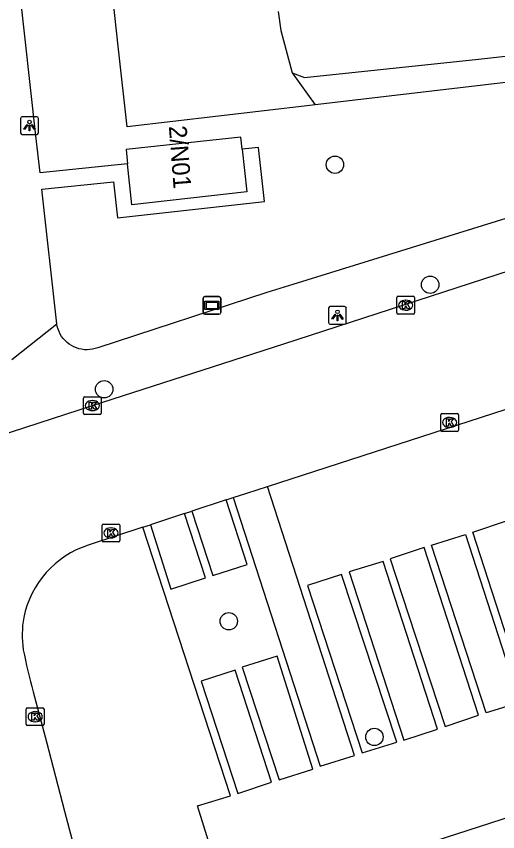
# Model space of a CAD drawing. Extents: x 161253 to 161848, y 384872 to 385383.
# Drawn here: x 161425.87 to 161452.98, y 385046.88 to 385092.79 of the extents above; entities that cross this region are included whole.
import ezdxf

# ---------------------------------------------------------------- set-up
doc = ezdxf.new("R2010")
doc.units = 0
for name, color, linetype in [('IMGEO_Boom', 7, 'Continuous'), ('IMGEO_Groenvoorziening', 7, 'Continuous'), ('IMGEO_Hek', 7, 'Continuous'), ('IMGEO_Kolk', 7, 'Continuous'), ('IMGEO_Lichtpunt', 7, 'Continuous'), ('IMGEO_Pand', 7, 'Continuous'), ('IMGEO_Pand_nummerreeks', 7, 'Continuous'), ('IMGEO_Parkeervlak_open', 7, 'Continuous'), ('IMGEO_Rijbaan_lokaal_open', 7, 'Continuous'), ('IMGEO_Verklikker', 7, 'Continuous'), ('IMGEO_Voetpad_open', 7, 'Continuous')]:
    doc.layers.add(name, color=color, linetype=linetype)

msp = doc.modelspace()

# ---------------------------------------------------------------- linework, layer by layer
at = {"layer": 'IMGEO_Boom'}
for centre in [(161443.813, 385084.433), (161449.173, 385077.674), (161430.819, 385071.789), (161437.837, 385058.731), (161446.031, 385052.213)]:
    msp.add_circle(centre, 0.489, dxfattribs=at)
at = {"layer": 'IMGEO_Groenvoorziening'}
for points in [[(161442.697, 385087.805), (161442.398, 385087.77), (161432.106, 385086.565), (161431.628, 385090.94), (161430.517, 385101.115), (161429.745, 385108.177), (161428.464, 385119.908), (161427.548, 385128.296), (161426.244, 385140.237), (161425.338, 385148.53), (161424.044, 385160.38), (161423.135, 385168.705), (161419.633, 385200.77)], [(161440.609, 385093.05), (161440.759, 385091.997), (161441.4, 385089.603)], [(161441.4, 385089.603), (161442.1, 385089.349), (161451.889, 385090.373), (161455.584, 385090.791), (161465.36, 385092.132), (161465.416, 385092.972)], [(161484.879, 385092.744), (161470.726, 385091.087), (161442.697, 385087.805)], [(161441.4, 385089.603), (161442.697, 385087.805)]]:
    msp.add_lwpolyline(points, dxfattribs=at)
at = {"layer": 'IMGEO_Hek'}
for points in [[(161431.628, 385090.94), (161430.517, 385101.115)], [(161432.106, 385086.565), (161431.628, 385090.94)], [(161470.726, 385091.087), (161442.697, 385087.805)], [(161442.398, 385087.77), (161432.106, 385086.565)], [(161442.697, 385087.805), (161442.398, 385087.77)]]:
    msp.add_lwpolyline(points, dxfattribs=at)
at = {"layer": 'IMGEO_Kolk'}
for p, q in [((161447.372, 385077.022), (161448.224, 385077.022)), ((161447.297, 385076.096), (161447.297, 385076.948)), ((161447.785, 385076.802), (161447.81, 385076.802)), ((161448.298, 385076.948), (161448.298, 385076.096)), ((161447.808, 385076.242), (161447.783, 385076.242)), ((161448.224, 385076.022), (161447.372, 385076.022)), ((161429.656, 385070.444), (161429.656, 385071.296)), ((161429.731, 385071.37), (161430.583, 385071.37)), ((161430.144, 385071.15), (161430.169, 385071.15)), ((161430.657, 385071.296), (161430.657, 385070.444)), ((161430.167, 385070.59), (161430.142, 385070.59)), ((161430.583, 385070.37), (161429.731, 385070.37)), ((161449.769, 385069.494), (161449.769, 385070.346)), ((161449.844, 385070.42), (161450.696, 385070.42)), ((161450.257, 385070.2), (161450.282, 385070.2)), ((161450.77, 385070.346), (161450.77, 385069.494)), ((161450.696, 385069.42), (161449.844, 385069.42)), ((161450.28, 385069.64), (161450.255, 385069.64)), ((161430.776, 385064.203), (161431.628, 385064.203)), ((161430.701, 385063.277), (161430.701, 385064.129)), ((161431.189, 385063.983), (161431.214, 385063.983)), ((161431.702, 385064.129), (161431.702, 385063.277)), ((161431.212, 385063.423), (161431.187, 385063.423)), ((161431.628, 385063.203), (161430.776, 385063.203)), ((161426.433, 385052.926), (161426.433, 385053.778)), ((161426.508, 385053.852), (161427.36, 385053.852)), ((161426.921, 385053.632), (161426.946, 385053.632)), ((161427.434, 385053.778), (161427.434, 385052.926)), ((161427.36, 385052.852), (161426.508, 385052.852)), ((161426.944, 385053.072), (161426.919, 385053.072))]:
    msp.add_line(p, q, dxfattribs=at)
for points in [[(161447.372, 385077.022), (161448.224, 385077.022)], [(161447.297, 385076.096), (161447.297, 385076.948)], [(161447.618, 385076.722), (161447.741, 385076.722), (161447.741, 385076.571), (161447.871, 385076.722), (161448.035, 385076.722), (161447.889, 385076.571), (161448.042, 385076.322), (161447.89, 385076.322), (161447.805, 385076.486), (161447.741, 385076.419), (161447.741, 385076.322), (161447.618, 385076.322), (161447.618, 385076.722)], [(161448.298, 385076.948), (161448.298, 385076.096)], [(161448.224, 385076.022), (161447.372, 385076.022)], [(161429.656, 385070.444), (161429.656, 385071.296)], [(161429.731, 385071.37), (161430.583, 385071.37)], [(161429.977, 385071.07), (161430.1, 385071.07), (161430.1, 385070.919), (161430.23, 385071.07), (161430.394, 385071.07), (161430.248, 385070.919), (161430.401, 385070.67), (161430.249, 385070.67), (161430.164, 385070.834), (161430.1, 385070.767), (161430.1, 385070.67), (161429.977, 385070.67), (161429.977, 385071.07)], [(161430.657, 385071.296), (161430.657, 385070.444)], [(161430.583, 385070.37), (161429.731, 385070.37)], [(161449.769, 385069.494), (161449.769, 385070.346)], [(161449.844, 385070.42), (161450.696, 385070.42)], [(161450.09, 385070.12), (161450.213, 385070.12), (161450.213, 385069.969), (161450.343, 385070.12), (161450.507, 385070.12), (161450.361, 385069.969), (161450.514, 385069.72), (161450.362, 385069.72), (161450.277, 385069.884), (161450.213, 385069.817), (161450.213, 385069.72), (161450.09, 385069.72), (161450.09, 385070.12)], [(161450.77, 385070.346), (161450.77, 385069.494)], [(161450.696, 385069.42), (161449.844, 385069.42)], [(161430.776, 385064.203), (161431.628, 385064.203)], [(161430.701, 385063.277), (161430.701, 385064.129)], [(161431.022, 385063.903), (161431.145, 385063.903), (161431.145, 385063.752), (161431.275, 385063.903), (161431.439, 385063.903), (161431.293, 385063.752), (161431.446, 385063.503), (161431.294, 385063.503), (161431.209, 385063.667), (161431.145, 385063.6), (161431.145, 385063.503), (161431.022, 385063.503), (161431.022, 385063.903)], [(161431.702, 385064.129), (161431.702, 385063.277)], [(161431.628, 385063.203), (161430.776, 385063.203)], [(161426.433, 385052.926), (161426.433, 385053.778)], [(161426.508, 385053.852), (161427.36, 385053.852)], [(161427.434, 385053.778), (161427.434, 385052.926)], [(161426.754, 385053.552), (161426.877, 385053.552), (161426.877, 385053.401), (161427.007, 385053.552), (161427.171, 385053.552), (161427.025, 385053.401), (161427.178, 385053.152), (161427.026, 385053.152), (161426.941, 385053.316), (161426.877, 385053.249), (161426.877, 385053.152), (161426.754, 385053.152), (161426.754, 385053.552)], [(161427.36, 385052.852), (161426.508, 385052.852)]]:
    msp.add_lwpolyline(points, dxfattribs=at)
for centre, start, end in [((161447.374, 385076.946), 91.552, 178.448), ((161447.374, 385076.946), 91.552, 178.448), ((161448.222, 385076.946), 1.552, 88.448), ((161448.222, 385076.946), 1.552, 88.448), ((161447.374, 385076.098), 181.552, 268.448), ((161447.374, 385076.098), 181.552, 268.448), ((161448.222, 385076.098), 271.552, 358.448), ((161448.222, 385076.098), 271.552, 358.448), ((161429.733, 385071.294), 91.552, 178.448), ((161429.733, 385071.294), 91.552, 178.448), ((161430.581, 385071.294), 1.552, 88.448), ((161430.581, 385071.294), 1.552, 88.448), ((161429.733, 385070.446), 181.552, 268.448), ((161429.733, 385070.446), 181.552, 268.448), ((161430.581, 385070.446), 271.552, 358.448), ((161430.581, 385070.446), 271.552, 358.448), ((161449.846, 385070.344), 91.552, 178.448), ((161449.846, 385070.344), 91.552, 178.448), ((161450.694, 385070.344), 1.552, 88.448), ((161450.694, 385070.344), 1.552, 88.448), ((161449.846, 385069.496), 181.552, 268.448), ((161449.846, 385069.496), 181.552, 268.448), ((161450.694, 385069.496), 271.552, 358.448), ((161450.694, 385069.496), 271.552, 358.448), ((161430.778, 385064.127), 91.552, 178.448), ((161430.778, 385064.127), 91.552, 178.448), ((161431.626, 385064.127), 1.552, 88.448), ((161431.626, 385064.127), 1.552, 88.448), ((161430.778, 385063.279), 181.552, 268.448), ((161430.778, 385063.279), 181.552, 268.448), ((161431.626, 385063.279), 271.552, 358.448), ((161431.626, 385063.279), 271.552, 358.448), ((161426.51, 385053.776), 91.552, 178.448), ((161426.51, 385053.776), 91.552, 178.448), ((161427.358, 385053.776), 1.552, 88.448), ((161427.358, 385053.776), 1.552, 88.448), ((161426.51, 385052.928), 181.552, 268.448), ((161426.51, 385052.928), 181.552, 268.448), ((161427.358, 385052.928), 271.552, 358.448), ((161427.358, 385052.928), 271.552, 358.448)]:
    msp.add_arc(centre, 0.0765, start, end, dxfattribs=at)
for centre, major_axis, ratio, start_param, end_param in [((161447.784, 385076.522), (-0.387, 0.002), 0.722429, 4.712389, 7.853982), ((161447.809, 385076.522), (-0.39, 0.002), 0.717154, 1.570796, 4.712389), ((161430.143, 385070.87), (-0.387, 0.002), 0.722429, 4.712389, 7.853982), ((161430.168, 385070.87), (-0.39, 0.002), 0.717154, 1.570796, 4.712389), ((161450.256, 385069.92), (-0.387, 0.002), 0.722429, 4.712389, 7.853982), ((161450.281, 385069.92), (-0.39, 0.002), 0.717154, 1.570796, 4.712389), ((161431.188, 385063.703), (-0.387, 0.002), 0.722429, 4.712389, 7.853982), ((161431.213, 385063.703), (-0.39, 0.002), 0.717154, 1.570796, 4.712389), ((161426.92, 385053.352), (-0.387, 0.002), 0.722429, 4.712389, 7.853982), ((161426.945, 385053.352), (-0.39, 0.002), 0.717154, 1.570796, 4.712389)]:
    msp.add_ellipse(centre, major_axis=major_axis, ratio=ratio, start_param=start_param, end_param=end_param, dxfattribs=at)
at = {"layer": 'IMGEO_Lichtpunt'}
for p, q in [((161427.02, 385087.133), (161426.212, 385087.133)), ((161427.02, 385087.133), (161426.212, 385087.133)), ((161426.118, 385087.038), (161426.118, 385086.231)), ((161426.118, 385087.038), (161426.118, 385086.231)), ((161427.114, 385086.231), (161427.114, 385087.038)), ((161427.114, 385086.231), (161427.114, 385087.038)), ((161426.212, 385086.137), (161427.02, 385086.137)), ((161426.212, 385086.137), (161427.02, 385086.137)), ((161443.457, 385076.353), (161443.457, 385075.546)), ((161443.457, 385076.353), (161443.457, 385075.546)), ((161444.359, 385076.448), (161443.551, 385076.448)), ((161444.359, 385076.448), (161443.551, 385076.448)), ((161444.453, 385075.546), (161444.453, 385076.353)), ((161444.453, 385075.546), (161444.453, 385076.353)), ((161443.551, 385075.452), (161444.359, 385075.452)), ((161443.551, 385075.452), (161444.359, 385075.452))]:
    msp.add_line(p, q, dxfattribs=at)
for points in [[(161426.492, 385086.702), (161426.531, 385086.674), (161426.343, 385086.412), (161426.305, 385086.439), (161426.492, 385086.702)], [(161426.594, 385086.654), (161426.641, 385086.654), (161426.641, 385086.332), (161426.594, 385086.332), (161426.594, 385086.654)], [(161426.704, 385086.674), (161426.742, 385086.701), (161426.929, 385086.439), (161426.89, 385086.411), (161426.704, 385086.674)], [(161443.831, 385076.017), (161443.87, 385075.989), (161443.682, 385075.727), (161443.644, 385075.754), (161443.831, 385076.017)], [(161443.933, 385075.969), (161443.98, 385075.969), (161443.98, 385075.647), (161443.933, 385075.647), (161443.933, 385075.969)], [(161444.043, 385075.989), (161444.081, 385076.016), (161444.268, 385075.754), (161444.229, 385075.726), (161444.043, 385075.989)]]:
    msp.add_lwpolyline(points, dxfattribs=at)
for centre in [(161426.617, 385086.836), (161443.956, 385076.151)]:
    msp.add_circle(centre, 0.0994, dxfattribs=at)
for centre, start, end in [((161426.212, 385087.038), 90, 180), ((161426.212, 385087.038), 90, 180), ((161427.02, 385087.038), 0, 90), ((161427.02, 385087.038), 0, 90), ((161426.212, 385086.231), 180, 270), ((161426.212, 385086.231), 180, 270), ((161427.02, 385086.231), 270, 0), ((161427.02, 385086.231), 270, 360), ((161443.551, 385076.353), 90, 180), ((161443.551, 385076.353), 90, 180), ((161444.359, 385076.353), 0, 90), ((161444.359, 385076.353), 0, 90), ((161443.551, 385075.546), 180, 270), ((161443.551, 385075.546), 180, 270), ((161444.359, 385075.546), 270, 0), ((161444.359, 385075.546), 270, 360)]:
    msp.add_arc(centre, 0.0946, start, end, dxfattribs=at)
at = {"layer": 'IMGEO_Pand'}
for points in [[(161438.589, 385085.303), (161438.514, 385085.978), (161432.049, 385085.283), (161432.136, 385084.473)], [(161438.589, 385085.303), (161438.857, 385082.906), (161432.384, 385082.18), (161432.136, 385084.473)]]:
    msp.add_lwpolyline(points, dxfattribs=at)
at = {"layer": 'IMGEO_Parkeervlak_open'}
for points in [[(161438.09, 385065.696), (161442.979, 385050.566), (161444.92, 385051.172), (161440.008, 385066.32)], [(161435.752, 385064.929), (161436.929, 385061.31), (161438.864, 385061.926), (161437.679, 385065.561)], [(161433.427, 385064.166), (161434.573, 385060.54), (161436.528, 385061.172), (161435.34, 385064.794)], [(161454.631, 385054.313), (161451.57, 385063.744), (161453.475, 385064.383), (161456.511, 385054.922), (161454.631, 385054.313)], [(161437.861, 385042.614), (161436.076, 385048.327), (161437.935, 385048.896), (161432.999, 385064.025)], [(161452.331, 385053.564), (161449.254, 385063.013), (161451.159, 385063.617), (161454.213, 385054.157), (161452.331, 385053.564)], [(161446.925, 385062.243), (161447.956, 385059.093), (161450.016, 385052.801), (161451.893, 385053.444), (161448.83, 385062.879), (161446.925, 385062.243)], [(161447.698, 385052.042), (161449.592, 385052.66), (161446.53, 385062.099), (161444.608, 385061.504), (161447.698, 385052.042)], [(161442.268, 385060.735), (161445.351, 385051.317), (161447.293, 385051.92), (161444.181, 385061.367), (161442.268, 385060.735)], [(161440.551, 385056.763), (161438.594, 385056.141), (161440.673, 385049.796), (161442.559, 385050.397), (161440.551, 385056.763)], [(161440.248, 385049.664), (161438.197, 385055.98), (161436.273, 385055.35), (161438.349, 385049.034), (161440.248, 385049.664)]]:
    msp.add_lwpolyline(points, dxfattribs=at)
at = {"layer": 'IMGEO_Rijbaan_lokaal_open'}
for points in [[(161410.636, 385064.527), (161417.274, 385066.689), (161430.157, 385070.87), (161440.926, 385074.344), (161460.453, 385080.682), (161469.526, 385083.633)], [(161440.008, 385066.32), (161456.059, 385071.513), (161471.347, 385076.545)], [(161438.09, 385065.696), (161438.843, 385065.943), (161440.008, 385066.32)], [(161437.679, 385065.561), (161435.752, 385064.929)], [(161437.679, 385065.561), (161438.09, 385065.696)], [(161435.34, 385064.794), (161433.427, 385064.166)], [(161435.34, 385064.794), (161435.752, 385064.929)], [(161432.999, 385064.025), (161433.427, 385064.166)], [(161432.999, 385064.025), (161429.917, 385063.014)], [(161426.814, 385054.752), (161427.573, 385051.945), (161428.592, 385048.045), (161429.019, 385046.404)], [(161470.434, 385053.161), (161452.512, 385047.336), (161439.031, 385042.98), (161437.861, 385042.614)]]:
    msp.add_lwpolyline(points, dxfattribs=at)
for centre, radius, start, end in [((161431.623, 385057.848), 5.441, 108.2773, 168.3333), ((161431.714, 385057.951), 5.51, 169.5708, 188.6054), ((161467.86, 385065.477), 42.424, 191.3527, 194.6436)]:
    msp.add_arc(centre, radius, start, end, dxfattribs=at)
at = {"layer": 'IMGEO_Verklikker'}
for p, q in [((161436.492, 385077.009), (161437.282, 385077.009)), ((161437.282, 385077.009), (161436.492, 385077.009)), ((161436.392, 385076.109), (161436.392, 385076.909)), ((161436.392, 385076.909), (161436.392, 385076.109)), ((161437.382, 385076.909), (161437.382, 385076.109)), ((161437.382, 385076.109), (161437.382, 385076.909)), ((161437.282, 385076.009), (161436.492, 385076.009)), ((161436.492, 385076.009), (161437.282, 385076.009))]:
    msp.add_line(p, q, dxfattribs=at)
for points in [[(161436.493, 385076.741), (161437.281, 385076.741), (161437.281, 385076.277), (161436.493, 385076.277), (161436.493, 385076.741)], [(161436.558, 385076.676), (161436.558, 385076.342), (161437.216, 385076.342), (161437.216, 385076.676), (161436.558, 385076.676)]]:
    msp.add_lwpolyline(points, dxfattribs=at)
for centre, start, end in [((161436.492, 385076.909), 90, 180), ((161436.492, 385076.909), 90, 180), ((161437.282, 385076.909), 0, 90), ((161437.282, 385076.909), 360, 90), ((161436.492, 385076.109), 180, 270), ((161436.492, 385076.109), 180, 270), ((161437.282, 385076.109), 270, 0), ((161437.282, 385076.109), 270, 0)]:
    msp.add_arc(centre, 0.1, start, end, dxfattribs=at)
at = {"layer": 'IMGEO_Voetpad_open'}
for points in [[(161432.136, 385084.473), (161427.209, 385083.967), (161426.978, 385086.052), (161418.12, 385166.146)], [(161469.66, 385086.431), (161441.446, 385077.688), (161439.983, 385077.235), (161430.465, 385074.128), (161430.455, 385074.124), (161430.309, 385074.076), (161430.16, 385074.041), (161430.009, 385074.02), (161429.856, 385074.012), (161429.703, 385074.018), (161429.551, 385074.038), (161429.401, 385074.071), (161429.255, 385074.117), (161429.114, 385074.176), (161428.979, 385074.248), (161428.85, 385074.331), (161428.73, 385074.425), (161428.618, 385074.53), (161428.516, 385074.645), (161428.425, 385074.768), (161428.345, 385074.898), (161428.278, 385075.036), (161428.222, 385075.178), (161428.18, 385075.326), (161428.151, 385075.476)], [(161428.151, 385075.476), (161427.314, 385083.055), (161431.343, 385083.465), (161431.579, 385081.436), (161439.843, 385082.364), (161439.505, 385085.406), (161438.589, 385085.303)], [(161425.628, 385073.461), (161428.151, 385075.476)]]:
    msp.add_lwpolyline(points, dxfattribs=at)

# ---------------------------------------------------------------- texts
at = {"layer": 'IMGEO_Pand_nummerreeks'}
msp.add_text('2/N01', height=1, rotation=274.3987, dxfattribs=at).set_placement((161434.459, 385086.601))

doc.saveas('drawing.dxf')
